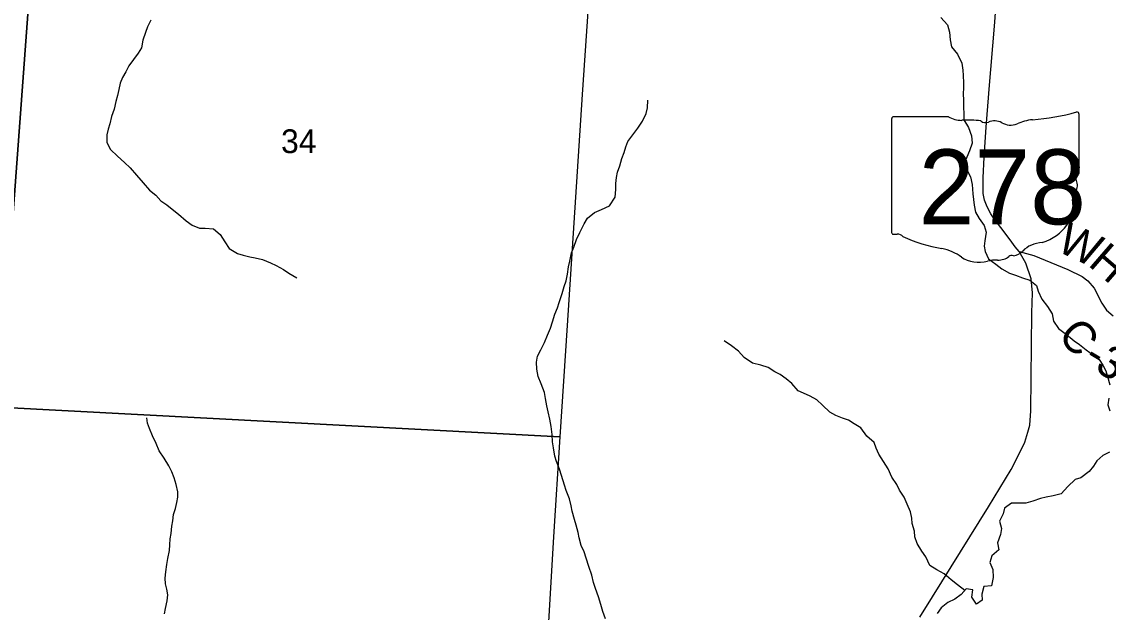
# Model space of a CAD drawing. Extents: x 0 to 34, y 0 to 22.
# Drawn here: x 26.642 to 28.554, y 15.55 to 16.59 of the extents above; entities that cross this region are included whole.
import ezdxf

# ---------------------------------------------------------------- set-up
doc = ezdxf.new("R2010")
doc.units = 0
for name, color, linetype in [('GM_X_County_Road', 7, 'Continuous'), ('GM_X_County_Road_Text', 7, 'Continuous'), ('GM_X_Minor_River', 7, 'Continuous'), ('GM_X_Section', 7, 'Continuous'), ('GM_X_Section_Text', 7, 'Continuous'), ('GM_X_State_Location', 7, 'Continuous'), ('GM_X_State_Route', 7, 'Continuous'), ('GM_X_State_Shield', 7, 'Continuous')]:
    doc.layers.add(name, color=color, linetype=linetype)

msp = doc.modelspace()

# ---------------------------------------------------------------- linework, layer by layer
at = {"layer": 'GM_X_County_Road'}
msp.add_lwpolyline([(28.3972, 16.1854), (28.4229, 16.1784), (28.4825, 16.1537), (28.508, 16.1412), (28.5176, 16.1339), (28.5288, 16.1209), (28.5424, 16.0943), (28.5504, 16.0823), (28.5624, 16.0722)], dxfattribs=at)
at = {"layer": 'GM_X_Minor_River'}
for points in [[(26.8695, 16.5927), (26.8638, 16.5806), (26.8601, 16.5711), (26.8552, 16.5574), (26.853, 16.5441), (26.8473, 16.5346), (26.839, 16.5233), (26.8307, 16.5122), (26.8255, 16.5016), (26.8198, 16.4917), (26.8157, 16.4819), (26.8131, 16.4705), (26.8108, 16.4602), (26.8082, 16.4496), (26.8049, 16.4356), (26.8004, 16.423), (26.7974, 16.4101), (26.7944, 16.4007), (26.7921, 16.3904), (26.7922, 16.3771), (26.7987, 16.365), (26.8108, 16.3529), (26.8233, 16.342), (26.8332, 16.3325), (26.8442, 16.3196), (26.856, 16.3064), (26.8674, 16.2935), (26.878, 16.2844), (26.8872, 16.2746), (26.8978, 16.2674), (26.9073, 16.2599), (26.9179, 16.2508), (26.9316, 16.2395), (26.9422, 16.2315), (26.9551, 16.2262), (26.9649, 16.2266), (26.9797, 16.2255), (26.9914, 16.2153), (26.9998, 16.2021), (27.0074, 16.1907), (27.0222, 16.1817), (27.0317, 16.1786), (27.0434, 16.176), (27.0533, 16.1742), (27.0662, 16.1711), (27.0798, 16.1651), (27.0897, 16.1606), (27.1026, 16.1538), (27.1124, 16.1474), (27.1261, 16.1391)], [(28.2594, 16.5973), (28.2708, 16.5844), (28.2747, 16.5715), (28.2755, 16.5582), (28.2778, 16.5457), (28.2888, 16.5325), (28.296, 16.517), (28.298, 16.5048), (28.2984, 16.4954), (28.2988, 16.4825), (28.2992, 16.473), (28.2985, 16.4635), (28.2989, 16.4514), (28.2993, 16.4407), (28.2997, 16.4263), (28.2998, 16.4169), (28.3078, 16.4036), (28.3131, 16.3888), (28.3143, 16.3759), (28.3098, 16.3627), (28.3049, 16.3513), (28.3004, 16.341), (28.3035, 16.3315), (28.3111, 16.3168), (28.3142, 16.3031), (28.3153, 16.2868), (28.3165, 16.2766), (28.3177, 16.2667), (28.32, 16.2546), (28.3265, 16.2432), (28.3356, 16.2308), (28.339, 16.2194), (28.3364, 16.2042), (28.3357, 16.1947), (28.3372, 16.1853), (28.3433, 16.1724), (28.3559, 16.1629), (28.3665, 16.155)], [(27.6693, 15.5386), (27.6644, 15.5515), (27.6609, 15.564), (27.6571, 15.5772), (27.6518, 15.592), (27.6483, 15.6026), (27.6452, 15.6155), (27.6399, 15.631), (27.6353, 15.6454), (27.6319, 15.6564), (27.6265, 15.6678), (27.6227, 15.6811), (27.6211, 15.6905), (27.6177, 15.7034), (27.6146, 15.7137), (27.6108, 15.7284), (27.6089, 15.7379), (27.6058, 15.7497), (27.6001, 15.7644), (27.597, 15.7739), (27.5921, 15.7913), (27.5882, 15.8019), (27.5833, 15.8156), (27.5802, 15.8251), (27.5779, 15.8395), (27.5763, 15.8501), (27.5752, 15.8633), (27.5736, 15.8774), (27.5713, 15.8903), (27.5682, 15.9031), (27.5663, 15.9138), (27.564, 15.9266), (27.5617, 15.9373), (27.5563, 15.9524), (27.551, 15.9653), (27.5483, 15.9782), (27.5479, 15.9907), (27.5497, 16.0013), (27.5554, 16.0123), (27.5621, 16.0249), (27.5674, 16.0381), (27.5723, 16.0503), (27.576, 16.0613), (27.5801, 16.0753), (27.5847, 16.086), (27.588, 16.0958), (27.5933, 16.1114), (27.5966, 16.1239), (27.6, 16.1334), (27.6023, 16.1455), (27.6045, 16.1581), (27.6063, 16.1683), (27.6097, 16.1831), (27.6138, 16.193), (27.6183, 16.2062), (27.624, 16.2188), (27.6315, 16.2343), (27.6375, 16.2438), (27.65, 16.2541), (27.6625, 16.2591), (27.6764, 16.2655), (27.6862, 16.2807), (27.6877, 16.2944), (27.6877, 16.305), (27.6888, 16.3156), (27.6906, 16.3251), (27.6944, 16.3361), (27.6981, 16.349), (27.7019, 16.3597), (27.7052, 16.3695), (27.7086, 16.379), (27.7154, 16.3885), (27.726, 16.4026), (27.7346, 16.4147), (27.7406, 16.4284), (27.7429, 16.4382), (27.7436, 16.4515)], [(28.3665, 16.155), (28.3798, 16.1471), (28.3904, 16.1437), (28.4029, 16.1392), (28.4158, 16.135), (28.4275, 16.1252), (28.4306, 16.1153), (28.4371, 16.1017), (28.447, 16.0888), (28.455, 16.0756), (28.4573, 16.0627), (28.4664, 16.0498), (28.4804, 16.0392), (28.4937, 16.0283), (28.5032, 16.0215), (28.515, 16.012), (28.5275, 16.0029), (28.5377, 15.995), (28.5442, 15.9852), (28.5492, 15.9753), (28.5522, 15.9655), (28.5564, 15.9507)], [(28.3015, 15.5887), (28.2888, 15.5985), (28.2774, 15.6076), (28.2649, 15.6182), (28.252, 15.625), (28.2399, 15.6329), (28.2326, 15.648), (28.2258, 15.6579), (28.2178, 15.6711), (28.2136, 15.6833), (28.2128, 15.6931), (28.209, 15.7064), (28.2082, 15.7159), (28.2059, 15.7272), (28.1998, 15.7405), (28.1944, 15.7526), (28.1864, 15.7655), (28.1819, 15.7753), (28.1731, 15.7882), (28.1663, 15.8026), (28.1583, 15.8155), (28.1499, 15.8283), (28.1457, 15.8393), (28.1419, 15.8492), (28.129, 15.8601), (28.1187, 15.8749), (28.1066, 15.8821), (28.0967, 15.8885), (28.0861, 15.8919), (28.0747, 15.8964), (28.0641, 15.9025), (28.0508, 15.9149), (28.0413, 15.924), (28.0296, 15.9308), (28.0178, 15.9361), (28.008, 15.9402), (27.9969, 15.9527), (27.9871, 15.9614), (27.9768, 15.969), (27.9673, 15.9735), (27.9552, 15.9811), (27.9423, 15.9852), (27.9276, 15.989), (27.9135, 15.9988), (27.9033, 16.0101), (27.8907, 16.0192), (27.8778, 16.0279)], [(28.5546, 15.9272), (28.5531, 15.9154), (28.5562, 15.9048)], [(26.8937, 15.5477), (26.8952, 15.5572), (26.8985, 15.5705), (26.8996, 15.5807), (26.8977, 15.5909), (26.8954, 15.6004), (26.8946, 15.6106), (26.8957, 15.6213), (26.8979, 15.6345), (26.8994, 15.6452), (26.9024, 15.6592), (26.9027, 15.6687), (26.9035, 15.6793), (26.9053, 15.6888), (26.9064, 15.7017), (26.9079, 15.7115), (26.9094, 15.7222), (26.9128, 15.7332), (26.9154, 15.7434), (26.9172, 15.7529), (26.9168, 15.7624), (26.9141, 15.7753), (26.9107, 15.787), (26.9065, 15.7972), (26.9012, 15.8078), (26.8928, 15.8215), (26.8844, 15.8343), (26.8791, 15.8472), (26.8722, 15.8609), (26.8669, 15.8737), (26.8638, 15.8832), (26.8623, 15.8927)], [(28.5557, 15.832), (28.544, 15.8263), (28.5334, 15.8171), (28.5277, 15.8073), (28.5202, 15.7978), (28.5055, 15.7871), (28.4956, 15.7841), (28.4828, 15.7715), (28.4711, 15.7586), (28.4568, 15.7551), (28.4443, 15.7528), (28.4344, 15.7505), (28.4208, 15.7456), (28.4087, 15.7425), (28.3951, 15.7421), (28.3837, 15.7425), (28.3713, 15.7337), (28.3687, 15.7238), (28.3623, 15.7105), (28.3657, 15.698), (28.3642, 15.6874), (28.3586, 15.6726), (28.3613, 15.6601), (28.3488, 15.6498), (28.3455, 15.6377), (28.3508, 15.6256), (28.3512, 15.6115), (28.3482, 15.5971), (28.335, 15.5956), (28.3313, 15.5823), (28.3321, 15.5713), (28.3222, 15.5645), (28.3135, 15.577), (28.3153, 15.5898), (28.304, 15.5913), (28.2949, 15.5818), (28.284, 15.5735), (28.2715, 15.5674), (28.2598, 15.5582), (28.253, 15.5484)]]:
    msp.add_lwpolyline(points, dxfattribs=at)
at = {"layer": 'GM_X_Section'}
for points in [[(25.6662, 16.9982), (26.6773, 16.93), (26.6015, 15.9112), (25.5991, 15.9654)], [(27.6556, 16.8655), (27.6283, 16.4618), (27.6018, 16.0551), (27.5892, 15.8592), (26.6015, 15.9112), (26.6773, 16.93)], [(26.6015, 15.9112), (27.5892, 15.8592), (27.5781, 15.6831), (27.5261, 14.8062), (26.5271, 14.8668)]]:
    msp.add_lwpolyline(points, close=True, dxfattribs=at)
at = {"layer": 'GM_X_State_Route'}
msp.add_lwpolyline([(28.222, 15.5416), (28.2447, 15.5773), (28.343, 15.7357), (28.3829, 15.8013), (28.3977, 15.8302), (28.4068, 15.8497), (28.4125, 15.8674), (28.4156, 15.8796), (28.4175, 15.9046), (28.4193, 16.0771), (28.4203, 16.1125), (28.418, 16.1375), (28.4086, 16.1648), (28.3972, 16.1854), (28.39, 16.1933), (28.381, 16.206), (28.3647, 16.2275), (28.3543, 16.2412), (28.3474, 16.2516), (28.3425, 16.2602), (28.3393, 16.2668), (28.3362, 16.2757), (28.3336, 16.2873), (28.3334, 16.2966), (28.3336, 16.3149), (28.3353, 16.3511), (28.3387, 16.4039), (28.3448, 16.4784), (28.347, 16.5059), (28.3541, 16.5891), (28.3558, 16.6145)], dxfattribs=at)
at = {"layer": 'GM_X_State_Shield'}
for p, q in [((28.1727, 16.4192), (28.1727, 16.219)), ((28.2724, 16.4226), (28.1759, 16.4226)), ((28.5023, 16.3229), (28.5023, 16.4276)), ((28.5022, 16.3229), (28.5023, 16.3229))]:
    msp.add_line(p, q, dxfattribs=at)
for centre, major_axis, start_param, end_param in [((28.1765, 16.4196), (0.00382, 0), 1.712693, 3.28349), ((28.2954, 16.4458), (0.037, 0), 4.042523, 4.731795), ((28.3849, 16.6954), (0.3495, 0), 4.814394, 5.042369), ((28.4986, 16.428), (0.00367, 0), 6.141152, 7.989035), ((28.3077, 16.3103), (0.133, 0), 1.404758, 1.657858), ((28.3379, 16.4206), (0.0107, 0), 3.836095, 5.185415), ((28.3536, 16.3975), (0.0222, 0), 0.950623, 2.079405), ((28.3822, 16.4292), (0.0267, 0), 4.081561, 5.145723), ((28.4294, 16.3615), (0.0703, 0), 1.699011, 2.107814), ((28.5014, 16.3152), (0.00568, 0), 1.883978, 3.671073), ((28.4653, 16.302), (0.0341, 0), 5.934695, 6.695948), ((28.4983, 16.3225), (0.00393, 0), 5.05454, 6.418171), ((28.5154, 16.2791), (0.0248, 0), 2.387724, 3.262537), ((28.4044, 16.2658), (0.0874, 0), 5.101752, 6.440018), ((28.1765, 16.2186), (0.00385, 0), 3.00124, 4.508301), ((28.1771, 16.2391), (0.0294, 0), 4.665946, 4.897461), ((28.1831, 16.2075), (0.0106, 0), 0.519207, 1.627899), ((28.3169, 16.3873), (0.2524, 0), 4.195997, 4.488961), ((28.2417, 16.1291), (0.079, 0), 0.823519, 1.323587), ((28.4413, 16.1629), (0.0479, 0), 1.647645, 2.488434), ((28.3271, 16.2065), (0.0501, 0), 4.026481, 4.996735), ((28.356, 16.1373), (0.0412, 0), 1.495662, 1.94098), ((28.3597, 16.1915), (0.0267, 0), 4.691044, 5.507374), ((28.3838, 16.1721), (0.00752, 0), 1.147584, 2.315152), ((28.3806, 16.1997), (0.0282, 0), 4.937069, 5.64225)]:
    msp.add_ellipse(centre, major_axis=major_axis, ratio=0.8, start_param=start_param, end_param=end_param, dxfattribs=at)

# ---------------------------------------------------------------- texts
at = {"layer": 'GM_X_County_Road_Text'}
for s, rotation, p in [('W', 334.8852, (28.4604, 16.1875)), ('H', 319.1869, (28.5165, 16.1618)), ('C', 311.0475, (28.4629, 16.037)), ('3', 327.2842, (28.5279, 15.9776)), ('-', 328.917, (28.5083, 15.9894))]:
    msp.add_text(s, height=0.0568, rotation=rotation, dxfattribs=at).set_placement(p)
at = {"layer": 'GM_X_Section_Text'}
msp.add_text('34', height=0.04186, rotation=0, dxfattribs=at).set_placement((27.0986, 16.3585))
at = {"layer": 'GM_X_State_Location'}
for s in ['r', 's']:
    msp.add_text(s, height=0.000189, dxfattribs=at).set_placement((28.3338, 16.3058))
msp.add_text('278', height=0.000189, rotation=0, dxfattribs=at).set_placement((28.2669, 16.292))
at = {"layer": 'GM_X_State_Shield'}
msp.add_text('278', height=0.13184, dxfattribs=at).set_placement((28.2203, 16.2332))

doc.saveas('drawing.dxf')
